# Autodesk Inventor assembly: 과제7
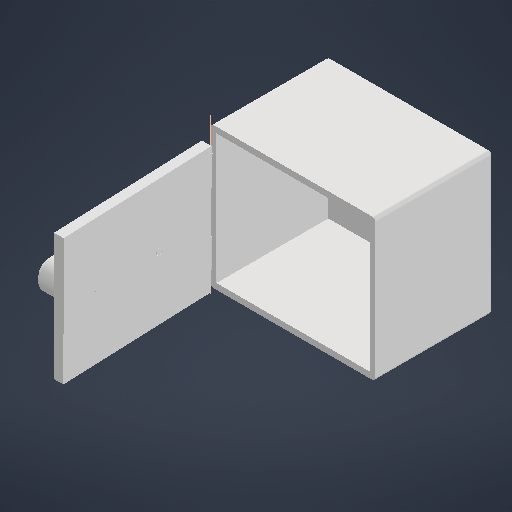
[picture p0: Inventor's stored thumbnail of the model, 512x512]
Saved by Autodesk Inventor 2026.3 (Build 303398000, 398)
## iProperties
Created: 2026-08
Part Number: 과제7
Document SubType Name: Assembly
Designer: chang
Author: chang
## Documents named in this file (6)
- C:\Users\chang\OneDrive\ROBIT_INTERN_INVENTOR(2)\과제7\과제7.iam
- C:\Users\chang\OneDrive\ROBIT_INTERN_INVENTOR(2)\과제7\금고 본체.ipt
- C:\Users\chang\OneDrive\ROBIT_INTERN_INVENTOR(2)\과제7\금고 문.ipt
- C:\Users\chang\OneDrive\ROBIT_INTERN_INVENTOR(2)\과제7\다이얼.ipt
- C:\Users\chang\OneDrive\ROBIT_INTERN_INVENTOR(2)\과제7\손잡이.ipt
- C:\Users\chang\OneDrive\ROBIT_INTERN_INVENTOR(2)\과제7\경첩.ipt
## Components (2 placed, 1 different names)
1. 경첩:1 — 강체:1
2. 경첩:2 — 강체:2
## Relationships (2: WeldJoint 2)
- 강체:1 [WeldJoint]: 경첩:1
- 강체:2 [WeldJoint]: 경첩:2
